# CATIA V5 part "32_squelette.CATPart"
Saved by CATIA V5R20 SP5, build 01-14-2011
Part number: 32_squelette
Publications: "module", "Z1", "Z2", "rapport", "delta1", "delta2", "L", "da1", "Plan.1", "Point.4", "Plan.2", "Point.5", "Point.6", "Point.9", "Esquisse.1", "Esquisse.2", "Point.1", "da2"
Bounding box of the stored display mesh (mm): x -40.294 to 40.294, y 2.913 to 33.362, z -70.57 to 40.294
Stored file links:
  C:\Documents and Settings\anizard\Bureau\13\32_squelette.CATPart
  C:\Documents and Settings\anizard\Bureau\13\anizard.CATProduct
  D:\Documents\T\2011-2012\CFAO\ThinkMotion\7\SqueletteV.CATPart
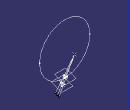
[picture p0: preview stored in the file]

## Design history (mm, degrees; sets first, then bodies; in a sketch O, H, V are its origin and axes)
Parameters
  module = 2 mm
  Z1 = 51
  Z2 = 20
  rapport = 2.55 {= Z1/Z2}
  delta1 = 68.587 deg {= atan(rapport)}
  delta2 = 21.413 deg {= atan(1/rapport)}
  L = 54.7814 mm {= ( module * Z1 / 2 ) / sin( delta1 )}
  da1 = 103.4604 mm {= module * Z1 + 2 * module * cos(delta1)}
  da2 = 43.7239 mm {= module * Z2 +2 * module * cos(delta2 )}
Set1
  Line1: linked copy from another document
  Point1: linked copy from another document
  Plane1: linked copy from another document
Body1 (main body)
  Point2: type OnCurve, Support Line1, RefPoint Point1, Length 33.3619 {= distance(Point1 ,Plane1 ) + da2  / 2 + 4mm}
  Line2: type Angle, RefPoint Point2, Curve Line1, Support yz-plane, Start 0, End 74.7814 {= L +20mm}, Angle 68.587 {= delta1}
  Line3: type Angle, RefPoint Point2, Curve Line2, Support yz-plane, Start 0, End 74.7814 {= L +20mm}, Angle -2.6147 {= -1.25*module /L}
  Line4: type Angle, RefPoint Point2, Curve Line2, Support yz-plane, Start 0, End 74.7814 {= L +20mm}, Angle 2.0918 {= module /L}
  Point3: type OnCurve, Support Line2, RefPoint Point2, Length 54.7814 {= L}
  Plane2: type Normal, Curve Line2, RefPoint Point3
  Point4: type OnCurve, Support Line2, RefPoint Point3, Length 14 {= module *7}
  Plane3: type Normal, Curve Line2, RefPoint Point4
  Point5: type OnCurve, Support Line4, RefPoint Point4, Length 0
  Point6: type OnCurve, Support Line3, RefPoint Point4, Length 0
  Point7: type OnCurve, Support Line4, RefPoint Point3, Length 0
  Point8: type OnCurve, Support Line3, RefPoint Point3, Length 0
  Sketch1 on Plane2, origin (0, -15.5532, -39.6607), H (-1, 0, 0), V (0, -0.931, 0.3651)
    point P1 (-2.3345, -33.1573)
    line L1 (-2.3345, -33.1573) -> (-0.6621, -28.5625)
    point P2 (-0.6621, -28.5625)
    line L2 (-0.6621, -28.5625) -> (0.6621, -28.5625)
    point P3 (0.6621, -28.5625)
    line L3 (0.6621, -28.5625) -> (2.3345, -33.1573)
    point P4 (2.3345, -33.1573)
    line L4 (2.3345, -33.1573) -> (-2.3345, -33.1573)
    reference projected point E1 (0, -28.5625) from Point8
    axis line L5 (-3.7619, -31.0591) -> (3.6633, -31.0591)
    reference projected point E2 (0, -31.0591) from Point2
    point P7 (1.5708, -31.0591)
    point P8 (-1.5708, -31.0591)
    reference projected point E3 (0, -33.0573) from Point7
    reference projected line E4 (0, 93.0973) -> (0, -93.0973) from Line1
    reference projected line E5 (0, 93.0973) -> (0, -93.0973) from Line1
    reference projected line E6 (0, 93.0973) -> (0, -93.0973) from Line1
    angle E6 L1 = 20
    distance P7 P8 = 3.1416 {= module * PI /2}
    distance L4 E3 = 0.1 {= module /20}
    horizontal: L2 H, L4 H, L5 H
    symmetry: P3 P2 E5, P4 P1 E4
    coincidence: L2 E1, L5 E2, P7 L3, P7 L5, P8 L1, P8 L5
  Sketch2 on Plane3, origin (0, -10.442, -26.6271), H (-1, 0, 0), V (0, -0.931, 0.3651)
    point P1 (-1.7472, -32.6466)
    line L1 (-1.7472, -32.6466) -> (-0.4929, -29.2006)
    point P2 (-0.4929, -29.2006)
    line L2 (-0.4929, -29.2006) -> (0.4929, -29.2006)
    point P3 (0.4929, -29.2006)
    line L3 (0.4929, -29.2006) -> (1.7472, -32.6466)
    point P4 (1.7472, -32.6466)
    line L4 (1.7472, -32.6466) -> (-1.7472, -32.6466)
    reference projected point E1 (0, -29.2006) from Point6
    axis line L5 (-4.3445, -31.0591) -> (4.7226, -31.0591)
    reference projected point E2 (0, -31.0591) from Point2
    point P7 (1.1694, -31.0591)
    point P8 (-1.1694, -31.0591)
    reference projected point E3 (0, -32.5466) from Point5
    reference projected line E4 (0, 93.0973) -> (0, -93.0973) from Line1
    reference projected line E5 (0, 93.0973) -> (0, -93.0973) from Line1
    reference projected line E6 (0, 93.0973) -> (0, -93.0973) from Line1
    distance P7 P8 = 2.3387 {= (L -7*module )*module *PI/L /2}
    angle L1 E6 = 20
    distance L4 E3 = 0.1 {= module /20}
    horizontal: L2 H, L4 H, L5 H
    symmetry: P3 P2 E5, P4 P1 E4
    coincidence: L2 E1, L5 E2, P7 L3, P7 L5, P8 L1, P8 L5
  Point9: type OnCurve, Support Line2, RefPoint Point3, Length 11.5 {= module *5.75}
  Circle1: type CenterAxis, Start 0, End 180, Pt Point9, Axis Line1, Radius 40.2938 {= distance(Point9 ,Line1 )}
